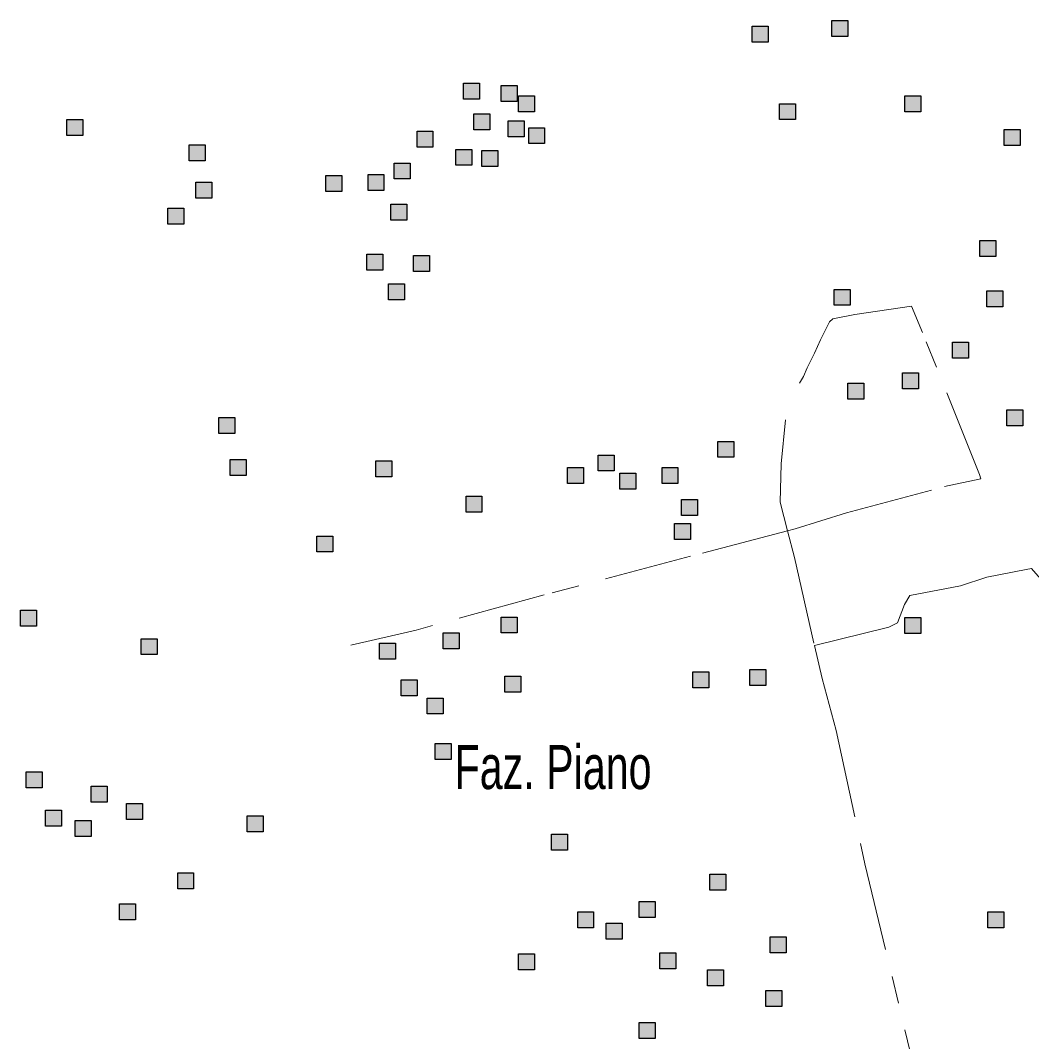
# Model space of a CAD drawing. Extents: x 445.4 to 500, y 8728.7 to 8784.
# Drawn here: x 449.252 to 452.927, y 8736.074 to 8739.783 of the extents above; entities that cross this region are included whole.
import ezdxf

# ---------------------------------------------------------------- set-up
doc = ezdxf.new("R2010")
doc.units = 0
doc.header["$LTSCALE"] = 0.064
doc.linetypes.add('DOT_DASHED', pattern=[7.7, 5, -1.2, 0.3, -1.2])
doc.layers.add('2', color=7, linetype='Continuous', lineweight=25)
doc.layers.add('22', color=7, linetype='DOT_DASHED', lineweight=13)
doc.layers.add('61', color=7, linetype='Continuous')

msp = doc.modelspace()

# ---------------------------------------------------------------- hatches: boundary and pattern name
at = {"layer": '2'}
for points in [[(452.2007, 8739.7835), (452.2587, 8739.7835), (452.2587, 8739.7255), (452.2007, 8739.7255)], [(451.9108, 8739.7627), (451.9688, 8739.7627), (451.9688, 8739.7047), (451.9108, 8739.7047)], [(450.862, 8739.5553), (450.92, 8739.5553), (450.92, 8739.4973), (450.862, 8739.4973)], [(450.9997, 8739.5473), (451.0577, 8739.5473), (451.0577, 8739.4893), (450.9997, 8739.4893)], [(451.0619, 8739.51), (451.1199, 8739.51), (451.1199, 8739.452), (451.0619, 8739.452)], [(452.0102, 8739.481), (452.0682, 8739.481), (452.0682, 8739.423), (452.0102, 8739.423)], [(452.4658, 8739.51), (452.5238, 8739.51), (452.5238, 8739.452), (452.4658, 8739.452)], [(450.9003, 8739.4437), (450.9583, 8739.4437), (450.9583, 8739.3857), (450.9003, 8739.3857)], [(449.4208, 8739.4239), (449.4788, 8739.4239), (449.4788, 8739.3659), (449.4208, 8739.3659)], [(451.0246, 8739.4188), (451.0826, 8739.4188), (451.0826, 8739.3608), (451.0246, 8739.3608)], [(450.6933, 8739.3815), (450.7513, 8739.3815), (450.7513, 8739.3235), (450.6933, 8739.3235)], [(451.0991, 8739.3939), (451.1571, 8739.3939), (451.1571, 8739.3359), (451.0991, 8739.3359)], [(452.8275, 8739.3877), (452.8855, 8739.3877), (452.8855, 8739.3297), (452.8275, 8739.3297)], [(449.865, 8739.3318), (449.923, 8739.3318), (449.923, 8739.2738), (449.865, 8739.2738)], [(450.8341, 8739.3152), (450.8921, 8739.3152), (450.8921, 8739.2572), (450.8341, 8739.2572)], [(450.9293, 8739.3111), (450.9873, 8739.3111), (450.9873, 8739.2531), (450.9293, 8739.2531)], [(450.6104, 8739.2655), (450.6684, 8739.2655), (450.6684, 8739.2075), (450.6104, 8739.2075)], [(450.362, 8739.2199), (450.42, 8739.2199), (450.42, 8739.1619), (450.362, 8739.1619)], [(450.5152, 8739.224), (450.5732, 8739.224), (450.5732, 8739.166), (450.5152, 8739.166)], [(449.8899, 8739.1963), (449.9479, 8739.1963), (449.9479, 8739.1383), (449.8899, 8739.1383)], [(450.598, 8739.1163), (450.656, 8739.1163), (450.656, 8739.0583), (450.598, 8739.0583)], [(449.7877, 8739.101), (449.8457, 8739.101), (449.8457, 8739.043), (449.7877, 8739.043)], [(452.7391, 8738.9837), (452.7971, 8738.9837), (452.7971, 8738.9257), (452.7391, 8738.9257)], [(450.5111, 8738.934), (450.5691, 8738.934), (450.5691, 8738.876), (450.5111, 8738.876)], [(450.6809, 8738.9298), (450.7389, 8738.9298), (450.7389, 8738.8718), (450.6809, 8738.8718)], [(450.5897, 8738.8262), (450.6477, 8738.8262), (450.6477, 8738.7682), (450.5897, 8738.7682)], [(452.2098, 8738.8066), (452.2678, 8738.8066), (452.2678, 8738.7486), (452.2098, 8738.7486)], [(452.7639, 8738.8014), (452.8219, 8738.8014), (452.8219, 8738.7434), (452.7639, 8738.7434)], [(452.6397, 8738.6149), (452.6977, 8738.6149), (452.6977, 8738.5569), (452.6397, 8738.5569)], [(452.4575, 8738.503), (452.5155, 8738.503), (452.5155, 8738.445), (452.4575, 8738.445)], [(452.2587, 8738.4657), (452.3167, 8738.4657), (452.3167, 8738.4077), (452.2587, 8738.4077)], [(452.8365, 8738.369), (452.8945, 8738.369), (452.8945, 8738.311), (452.8365, 8738.311)], [(449.9727, 8738.3414), (450.0307, 8738.3414), (450.0307, 8738.2834), (449.9727, 8738.2834)], [(451.7866, 8738.2544), (451.8446, 8738.2544), (451.8446, 8738.1964), (451.7866, 8738.1964)], [(450.0141, 8738.1881), (450.0721, 8738.1881), (450.0721, 8738.1301), (450.0141, 8738.1301)], [(450.5442, 8738.1839), (450.6022, 8738.1839), (450.6022, 8738.1259), (450.5442, 8738.1259)], [(451.3517, 8738.2047), (451.4097, 8738.2047), (451.4097, 8738.1467), (451.3517, 8738.1467)], [(451.2399, 8738.1591), (451.2979, 8738.1591), (451.2979, 8738.1011), (451.2399, 8738.1011)], [(451.5837, 8738.1591), (451.6417, 8738.1591), (451.6417, 8738.1011), (451.5837, 8738.1011)], [(451.4304, 8738.1384), (451.4884, 8738.1384), (451.4884, 8738.0804), (451.4304, 8738.0804)], [(450.8714, 8738.0555), (450.9294, 8738.0555), (450.9294, 8737.9975), (450.8714, 8737.9975)], [(451.6541, 8738.0431), (451.7121, 8738.0431), (451.7121, 8737.9851), (451.6541, 8737.9851)], [(451.6292, 8737.956), (451.6872, 8737.956), (451.6872, 8737.898), (451.6292, 8737.898)], [(450.3288, 8737.9105), (450.3868, 8737.9105), (450.3868, 8737.8525), (450.3288, 8737.8525)], [(449.2521, 8737.6411), (449.3101, 8737.6411), (449.3101, 8737.5831), (449.2521, 8737.5831)], [(450.9997, 8737.6162), (451.0577, 8737.6162), (451.0577, 8737.5582), (450.9997, 8737.5582)], [(452.4658, 8737.6146), (452.5238, 8737.6146), (452.5238, 8737.5566), (452.4658, 8737.5566)], [(450.7885, 8737.5582), (450.8465, 8737.5582), (450.8465, 8737.5002), (450.7885, 8737.5002)], [(449.6911, 8737.5375), (449.7491, 8737.5375), (449.7491, 8737.4795), (449.6911, 8737.4795)], [(450.5566, 8737.5209), (450.6146, 8737.5209), (450.6146, 8737.4629), (450.5566, 8737.4629)], [(451.0122, 8737.4008), (451.0702, 8737.4008), (451.0702, 8737.3428), (451.0122, 8737.3428)], [(451.6955, 8737.4173), (451.7535, 8737.4173), (451.7535, 8737.3593), (451.6955, 8737.3593)], [(451.9025, 8737.4256), (451.9605, 8737.4256), (451.9605, 8737.3676), (451.9025, 8737.3676)], [(450.6353, 8737.3883), (450.6933, 8737.3883), (450.6933, 8737.3303), (450.6353, 8737.3303)], [(450.7305, 8737.322), (450.7885, 8737.322), (450.7885, 8737.264), (450.7305, 8737.264)], [(450.7595, 8737.1571), (450.8175, 8737.1571), (450.8175, 8737.0991), (450.7595, 8737.0991)], [(449.2728, 8737.0535), (449.3308, 8737.0535), (449.3308, 8736.9955), (449.2728, 8736.9955)], [(449.5089, 8737.0013), (449.5669, 8737.0013), (449.5669, 8736.9433), (449.5089, 8736.9433)], [(449.6372, 8736.9391), (449.6952, 8736.9391), (449.6952, 8736.8811), (449.6372, 8736.8811)], [(449.3432, 8736.9143), (449.4012, 8736.9143), (449.4012, 8736.8563), (449.3432, 8736.8563)], [(450.0762, 8736.8936), (450.1342, 8736.8936), (450.1342, 8736.8356), (450.0762, 8736.8356)], [(449.4509, 8736.877), (449.5089, 8736.877), (449.5089, 8736.819), (449.4509, 8736.819)], [(451.182, 8736.8273), (451.24, 8736.8273), (451.24, 8736.7693), (451.182, 8736.7693)], [(449.8236, 8736.6864), (449.8816, 8736.6864), (449.8816, 8736.6284), (449.8236, 8736.6284)], [(451.7576, 8736.6822), (451.8156, 8736.6822), (451.8156, 8736.6242), (451.7576, 8736.6242)], [(449.6124, 8736.5745), (449.6704, 8736.5745), (449.6704, 8736.5165), (449.6124, 8736.5165)], [(451.5008, 8736.5828), (451.5588, 8736.5828), (451.5588, 8736.5248), (451.5008, 8736.5248)], [(451.2772, 8736.5455), (451.3352, 8736.5455), (451.3352, 8736.4875), (451.2772, 8736.4875)], [(452.7681, 8736.5455), (452.8261, 8736.5455), (452.8261, 8736.4875), (452.7681, 8736.4875)], [(451.3807, 8736.504), (451.4387, 8736.504), (451.4387, 8736.446), (451.3807, 8736.446)], [(451.9771, 8736.4543), (452.0351, 8736.4543), (452.0351, 8736.3963), (451.9771, 8736.3963)], [(451.0619, 8736.3922), (451.1199, 8736.3922), (451.1199, 8736.3342), (451.0619, 8736.3342)], [(451.5754, 8736.3963), (451.6334, 8736.3963), (451.6334, 8736.3383), (451.5754, 8736.3383)], [(451.7493, 8736.3341), (451.8073, 8736.3341), (451.8073, 8736.2761), (451.7493, 8736.2761)], [(451.9605, 8736.2596), (452.0185, 8736.2596), (452.0185, 8736.2016), (451.9605, 8736.2016)], [(451.5008, 8736.1435), (451.5588, 8736.1435), (451.5588, 8736.0855), (451.5008, 8736.0855)]]:
    msp.add_hatch(color=256, dxfattribs=at).paths.add_polyline_path(points)

# ---------------------------------------------------------------- linework, layer by layer
for points in [[(452.2007, 8739.7835), (452.2587, 8739.7835), (452.2587, 8739.7255), (452.2007, 8739.7255)], [(451.9108, 8739.7627), (451.9688, 8739.7627), (451.9688, 8739.7047), (451.9108, 8739.7047)], [(450.862, 8739.5553), (450.92, 8739.5553), (450.92, 8739.4973), (450.862, 8739.4973)], [(450.9997, 8739.5473), (451.0577, 8739.5473), (451.0577, 8739.4893), (450.9997, 8739.4893)], [(451.0619, 8739.51), (451.1199, 8739.51), (451.1199, 8739.452), (451.0619, 8739.452)], [(452.0102, 8739.481), (452.0682, 8739.481), (452.0682, 8739.423), (452.0102, 8739.423)], [(452.4658, 8739.51), (452.5238, 8739.51), (452.5238, 8739.452), (452.4658, 8739.452)], [(450.9003, 8739.4437), (450.9583, 8739.4437), (450.9583, 8739.3857), (450.9003, 8739.3857)], [(449.4208, 8739.4239), (449.4788, 8739.4239), (449.4788, 8739.3659), (449.4208, 8739.3659)], [(451.0246, 8739.4188), (451.0826, 8739.4188), (451.0826, 8739.3608), (451.0246, 8739.3608)], [(450.6933, 8739.3815), (450.7513, 8739.3815), (450.7513, 8739.3235), (450.6933, 8739.3235)], [(451.0991, 8739.3939), (451.1571, 8739.3939), (451.1571, 8739.3359), (451.0991, 8739.3359)], [(452.8275, 8739.3877), (452.8855, 8739.3877), (452.8855, 8739.3297), (452.8275, 8739.3297)], [(449.865, 8739.3318), (449.923, 8739.3318), (449.923, 8739.2738), (449.865, 8739.2738)], [(450.8341, 8739.3152), (450.8921, 8739.3152), (450.8921, 8739.2572), (450.8341, 8739.2572)], [(450.9293, 8739.3111), (450.9873, 8739.3111), (450.9873, 8739.2531), (450.9293, 8739.2531)], [(450.6104, 8739.2655), (450.6684, 8739.2655), (450.6684, 8739.2075), (450.6104, 8739.2075)], [(450.362, 8739.2199), (450.42, 8739.2199), (450.42, 8739.1619), (450.362, 8739.1619)], [(450.5152, 8739.224), (450.5732, 8739.224), (450.5732, 8739.166), (450.5152, 8739.166)], [(449.8899, 8739.1963), (449.9479, 8739.1963), (449.9479, 8739.1383), (449.8899, 8739.1383)], [(450.598, 8739.1163), (450.656, 8739.1163), (450.656, 8739.0583), (450.598, 8739.0583)], [(449.7877, 8739.101), (449.8457, 8739.101), (449.8457, 8739.043), (449.7877, 8739.043)], [(452.7391, 8738.9837), (452.7971, 8738.9837), (452.7971, 8738.9257), (452.7391, 8738.9257)], [(450.5111, 8738.934), (450.5691, 8738.934), (450.5691, 8738.876), (450.5111, 8738.876)], [(450.6809, 8738.9298), (450.7389, 8738.9298), (450.7389, 8738.8718), (450.6809, 8738.8718)], [(450.5897, 8738.8262), (450.6477, 8738.8262), (450.6477, 8738.7682), (450.5897, 8738.7682)], [(452.2098, 8738.8066), (452.2678, 8738.8066), (452.2678, 8738.7486), (452.2098, 8738.7486)], [(452.7639, 8738.8014), (452.8219, 8738.8014), (452.8219, 8738.7434), (452.7639, 8738.7434)], [(452.6397, 8738.6149), (452.6977, 8738.6149), (452.6977, 8738.5569), (452.6397, 8738.5569)], [(452.4575, 8738.503), (452.5155, 8738.503), (452.5155, 8738.445), (452.4575, 8738.445)], [(452.2587, 8738.4657), (452.3167, 8738.4657), (452.3167, 8738.4077), (452.2587, 8738.4077)], [(452.8365, 8738.369), (452.8945, 8738.369), (452.8945, 8738.311), (452.8365, 8738.311)], [(449.9727, 8738.3414), (450.0307, 8738.3414), (450.0307, 8738.2834), (449.9727, 8738.2834)], [(451.7866, 8738.2544), (451.8446, 8738.2544), (451.8446, 8738.1964), (451.7866, 8738.1964)], [(450.0141, 8738.1881), (450.0721, 8738.1881), (450.0721, 8738.1301), (450.0141, 8738.1301)], [(450.5442, 8738.1839), (450.6022, 8738.1839), (450.6022, 8738.1259), (450.5442, 8738.1259)], [(451.3517, 8738.2047), (451.4097, 8738.2047), (451.4097, 8738.1467), (451.3517, 8738.1467)], [(451.2399, 8738.1591), (451.2979, 8738.1591), (451.2979, 8738.1011), (451.2399, 8738.1011)], [(451.5837, 8738.1591), (451.6417, 8738.1591), (451.6417, 8738.1011), (451.5837, 8738.1011)], [(451.4304, 8738.1384), (451.4884, 8738.1384), (451.4884, 8738.0804), (451.4304, 8738.0804)], [(450.8714, 8738.0555), (450.9294, 8738.0555), (450.9294, 8737.9975), (450.8714, 8737.9975)], [(451.6541, 8738.0431), (451.7121, 8738.0431), (451.7121, 8737.9851), (451.6541, 8737.9851)], [(451.6292, 8737.956), (451.6872, 8737.956), (451.6872, 8737.898), (451.6292, 8737.898)], [(450.3288, 8737.9105), (450.3868, 8737.9105), (450.3868, 8737.8525), (450.3288, 8737.8525)], [(449.2521, 8737.6411), (449.3101, 8737.6411), (449.3101, 8737.5831), (449.2521, 8737.5831)], [(450.9997, 8737.6162), (451.0577, 8737.6162), (451.0577, 8737.5582), (450.9997, 8737.5582)], [(452.4658, 8737.6146), (452.5238, 8737.6146), (452.5238, 8737.5566), (452.4658, 8737.5566)], [(450.7885, 8737.5582), (450.8465, 8737.5582), (450.8465, 8737.5002), (450.7885, 8737.5002)], [(449.6911, 8737.5375), (449.7491, 8737.5375), (449.7491, 8737.4795), (449.6911, 8737.4795)], [(450.5566, 8737.5209), (450.6146, 8737.5209), (450.6146, 8737.4629), (450.5566, 8737.4629)], [(451.0122, 8737.4008), (451.0702, 8737.4008), (451.0702, 8737.3428), (451.0122, 8737.3428)], [(451.6955, 8737.4173), (451.7535, 8737.4173), (451.7535, 8737.3593), (451.6955, 8737.3593)], [(451.9025, 8737.4256), (451.9605, 8737.4256), (451.9605, 8737.3676), (451.9025, 8737.3676)], [(450.6353, 8737.3883), (450.6933, 8737.3883), (450.6933, 8737.3303), (450.6353, 8737.3303)], [(450.7305, 8737.322), (450.7885, 8737.322), (450.7885, 8737.264), (450.7305, 8737.264)], [(450.7595, 8737.1571), (450.8175, 8737.1571), (450.8175, 8737.0991), (450.7595, 8737.0991)], [(449.2728, 8737.0535), (449.3308, 8737.0535), (449.3308, 8736.9955), (449.2728, 8736.9955)], [(449.5089, 8737.0013), (449.5669, 8737.0013), (449.5669, 8736.9433), (449.5089, 8736.9433)], [(449.6372, 8736.9391), (449.6952, 8736.9391), (449.6952, 8736.8811), (449.6372, 8736.8811)], [(449.3432, 8736.9143), (449.4012, 8736.9143), (449.4012, 8736.8563), (449.3432, 8736.8563)], [(450.0762, 8736.8936), (450.1342, 8736.8936), (450.1342, 8736.8356), (450.0762, 8736.8356)], [(449.4509, 8736.877), (449.5089, 8736.877), (449.5089, 8736.819), (449.4509, 8736.819)], [(451.182, 8736.8273), (451.24, 8736.8273), (451.24, 8736.7693), (451.182, 8736.7693)], [(449.8236, 8736.6864), (449.8816, 8736.6864), (449.8816, 8736.6284), (449.8236, 8736.6284)], [(451.7576, 8736.6822), (451.8156, 8736.6822), (451.8156, 8736.6242), (451.7576, 8736.6242)], [(449.6124, 8736.5745), (449.6704, 8736.5745), (449.6704, 8736.5165), (449.6124, 8736.5165)], [(451.5008, 8736.5828), (451.5588, 8736.5828), (451.5588, 8736.5248), (451.5008, 8736.5248)], [(451.2772, 8736.5455), (451.3352, 8736.5455), (451.3352, 8736.4875), (451.2772, 8736.4875)], [(452.7681, 8736.5455), (452.8261, 8736.5455), (452.8261, 8736.4875), (452.7681, 8736.4875)], [(451.3807, 8736.504), (451.4387, 8736.504), (451.4387, 8736.446), (451.3807, 8736.446)], [(451.9771, 8736.4543), (452.0351, 8736.4543), (452.0351, 8736.3963), (451.9771, 8736.3963)], [(451.0619, 8736.3922), (451.1199, 8736.3922), (451.1199, 8736.3342), (451.0619, 8736.3342)], [(451.5754, 8736.3963), (451.6334, 8736.3963), (451.6334, 8736.3383), (451.5754, 8736.3383)], [(451.7493, 8736.3341), (451.8073, 8736.3341), (451.8073, 8736.2761), (451.7493, 8736.2761)], [(451.9605, 8736.2596), (452.0185, 8736.2596), (452.0185, 8736.2016), (451.9605, 8736.2016)], [(451.5008, 8736.1435), (451.5588, 8736.1435), (451.5588, 8736.0855), (451.5008, 8736.0855)]]:
    msp.add_lwpolyline(points, close=True, dxfattribs=at)
at = {"layer": '22'}
for points in [[(452.0399, 8737.9293), (452.0678, 8737.9366), (452.2535, 8737.9943), (452.6098, 8738.0902), (452.7419, 8738.1182), (452.7379, 8738.1342), (452.5297, 8738.6499), (452.4897, 8738.7459)], [(452.4897, 8738.7459), (452.2839, 8738.7148), (452.2042, 8738.6991), (452.1924, 8738.6886), (452.1597, 8738.6232), (452.1375, 8738.5749), (452.1114, 8738.5212), (452.0983, 8738.4899), (452.0838, 8738.4658)], [(452.0329, 8738.3328), (452.0169, 8738.1728), (452.0129, 8738.0329), (452.0399, 8737.9293)], [(452.0399, 8737.9293), (451.6875, 8737.8367), (451.1551, 8737.6967), (450.6907, 8737.5688), (450.4531, 8737.5141)], [(452.0399, 8737.9293), (452.0649, 8737.833), (452.1377, 8737.5131)], [(452.1377, 8737.5131), (452.4074, 8737.5796), (452.4393, 8737.5955), (452.4647, 8737.6623), (452.4838, 8737.6941), (452.6684, 8737.729), (452.7639, 8737.7608), (452.9071, 8737.7894), (452.9262, 8737.7926), (452.9676, 8737.7449), (452.9803, 8737.7354), (453.219, 8737.7958), (453.41, 8737.8466), (453.5, 8737.8676)], [(452.1377, 8737.5131), (452.165, 8737.3932), (452.2167, 8737.2037), (452.3212, 8736.7192), (452.5098, 8735.9368), (452.6379, 8735.393), (452.6704, 8735.2263), (452.6704, 8735.1383), (452.6413, 8734.5432)]]:
    msp.add_lwpolyline(points, dxfattribs=at)

# ---------------------------------------------------------------- texts
at = {"layer": '61', "width": 0.7}
msp.add_text('Faz. Piano', height=0.16, dxfattribs=at).set_placement((450.8297, 8736.9912))

doc.saveas('drawing.dxf')
